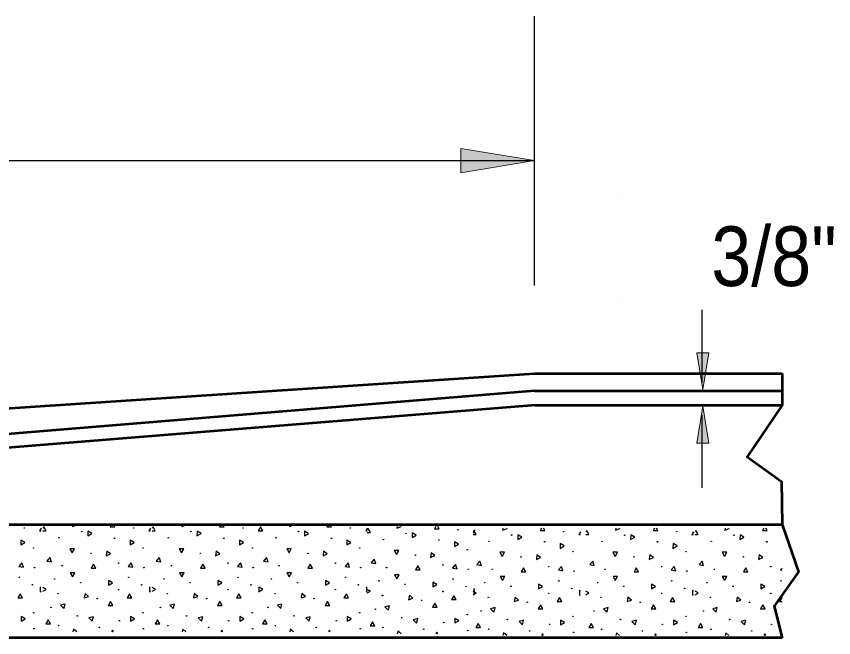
# Model space of a CAD drawing. Extents: x 75.6 to 110.9, y 28 to 50.
# Drawn here: x 100.368 to 102.421, y 39.251 to 40.813 of the extents above; entities that cross this region are included whole.
import ezdxf
from ezdxf.enums import TextEntityAlignment as Align

# ---------------------------------------------------------------- set-up
doc = ezdxf.new("R2010")
doc.units = 0
doc.header["$LTSCALE"] = 0.06
doc.layers.add('1', color=7, linetype='Continuous', lineweight=25)
doc.layers.add('3', color=7, linetype='Continuous', lineweight=13)

msp = doc.modelspace()

# ---------------------------------------------------------------- hatches: boundary and pattern name
at = {"layer": '3'}
for points in [[(101.48483, 40.48075), (101.48483, 40.41925), (101.66942, 40.45), (101.66942, 40.45)], [(102.07725, 39.96658), (102.108, 39.96658), (102.09258, 39.87433), (102.09258, 39.87433)], [(102.07725, 39.74), (102.108, 39.74), (102.09258, 39.83233), (102.09258, 39.83233)]]:
    msp.add_hatch(color=256, dxfattribs=at).paths.add_polyline_path(points)

# ---------------------------------------------------------------- linework, layer by layer
at = {"layer": '1'}
for p, q in [((101.66942, 40.13592), (101.66942, 40.81275)), ((98.68033, 40.45), (101.66942, 40.45)), ((100.4305, 39.52617), (100.42658, 39.51933)), ((100.42658, 39.51933), (100.4305, 39.51933)), ((100.437, 39.52933), (100.43508, 39.52617)), ((100.43508, 39.51933), (100.44283, 39.51933)), ((100.44283, 39.51933), (100.437, 39.52933)), ((100.51033, 39.535), (100.50958, 39.53033)), ((100.50958, 39.53033), (100.5205, 39.53433)), ((100.5205, 39.53433), (100.51983, 39.535)), ((100.60733, 39.535), (100.604, 39.52917)), ((100.604, 39.52917), (100.61558, 39.52917)), ((100.61558, 39.52917), (100.61225, 39.535)), ((100.70508, 39.52617), (100.70117, 39.51933)), ((100.70117, 39.51933), (100.70508, 39.51933)), ((100.71158, 39.52933), (100.70958, 39.52617)), ((100.70958, 39.51933), (100.71733, 39.51933)), ((100.71733, 39.51933), (100.71158, 39.52933)), ((100.78492, 39.535), (100.78408, 39.53033)), ((100.78408, 39.53033), (100.795, 39.53433)), ((100.795, 39.53433), (100.79433, 39.535)), ((100.88192, 39.535), (100.87858, 39.52917)), ((100.87858, 39.52917), (100.89025, 39.52917)), ((100.89025, 39.52917), (100.88683, 39.535)), ((100.97958, 39.52617), (100.97567, 39.51933)), ((100.97567, 39.51933), (100.97958, 39.51933)), ((100.98158, 39.52933), (100.97975, 39.52617)), ((100.97975, 39.51933), (100.98742, 39.51933)), ((100.98742, 39.51933), (100.98158, 39.52933)), ((101.055, 39.535), (101.05425, 39.53033)), ((101.05425, 39.53033), (101.06517, 39.53433)), ((101.06517, 39.53433), (101.06442, 39.535)), ((101.152, 39.535), (101.14858, 39.52917)), ((101.14858, 39.52917), (101.16025, 39.52917)), ((101.16025, 39.52917), (101.15692, 39.535)), ((101.24975, 39.52617), (101.24583, 39.51933)), ((101.24583, 39.51933), (101.24975, 39.51933)), ((101.25167, 39.52492), (101.24983, 39.52167)), ((101.2575, 39.51483), (101.25167, 39.52492)), ((101.325, 39.53042), (101.32425, 39.52592)), ((101.32425, 39.52592), (101.33525, 39.52992)), ((101.33525, 39.52992), (101.3345, 39.53042)), ((101.422, 39.53042), (101.41867, 39.52467)), ((101.41867, 39.52467), (101.43033, 39.52467)), ((101.43033, 39.52467), (101.427, 39.53042)), ((101.51725, 39.52033), (101.51542, 39.51708)), ((101.51983, 39.52167), (101.51583, 39.51483)), ((101.52308, 39.51033), (101.51725, 39.52033)), ((101.59058, 39.52592), (101.58983, 39.52133)), ((101.58983, 39.52133), (101.60083, 39.52533)), ((101.60083, 39.52533), (101.60008, 39.52592)), ((101.68758, 39.52592), (101.68425, 39.52017)), ((101.68425, 39.52017), (101.69592, 39.52017)), ((101.69592, 39.52017), (101.69258, 39.52592)), ((101.80083, 39.52033), (101.79892, 39.51708)), ((101.80658, 39.51033), (101.80083, 39.52033)), ((101.87425, 39.52592), (101.87342, 39.52133)), ((101.87342, 39.52133), (101.88433, 39.52533)), ((101.88433, 39.52533), (101.88358, 39.52592)), ((101.97125, 39.52592), (101.96783, 39.52017)), ((101.96783, 39.52017), (101.9795, 39.52017)), ((101.9795, 39.52017), (101.97617, 39.52592)), ((102.07542, 39.52033), (102.07358, 39.51708)), ((102.08125, 39.51033), (102.07542, 39.52033)), ((102.14883, 39.52592), (102.148, 39.52133)), ((102.148, 39.52133), (102.15892, 39.52533)), ((102.15892, 39.52533), (102.15825, 39.52592)), ((102.24583, 39.52592), (102.24242, 39.52017)), ((102.24242, 39.52017), (102.25408, 39.52017)), ((102.25408, 39.52017), (102.25075, 39.52592)), ((101.24983, 39.51483), (101.2575, 39.51483)), ((101.51542, 39.51033), (101.52308, 39.51033)), ((101.51583, 39.51483), (101.51983, 39.51483)), ((101.78542, 39.51708), (101.78142, 39.51033)), ((101.78142, 39.51033), (101.78542, 39.51033)), ((101.79892, 39.51033), (101.80658, 39.51033)), ((102.06892, 39.51708), (102.065, 39.51033)), ((102.065, 39.51033), (102.06892, 39.51033)), ((102.07358, 39.51033), (102.08125, 39.51033)), ((102.29183, 39.42575), (102.28783, 39.421)), ((102.28783, 39.421), (102.29183, 39.42033)), ((100.42825, 39.378), (100.42817, 39.36633)), ((100.42825, 39.378), (100.42817, 39.36633)), ((100.4305, 39.37658), (100.42825, 39.378)), ((100.4305, 39.37658), (100.42825, 39.378)), ((100.70283, 39.378), (100.70275, 39.36633)), ((100.70283, 39.378), (100.70275, 39.36633)), ((100.70508, 39.37658), (100.70283, 39.378)), ((100.70508, 39.37658), (100.70283, 39.378)), ((100.97733, 39.378), (100.97725, 39.36633)), ((100.97733, 39.378), (100.97725, 39.36633)), ((100.97958, 39.37658), (100.97733, 39.378)), ((100.97958, 39.37658), (100.97733, 39.378)), ((101.24742, 39.378), (101.24742, 39.36633)), ((101.24742, 39.378), (101.24742, 39.36633)), ((101.24975, 39.37658), (101.24742, 39.378)), ((101.24975, 39.37658), (101.24742, 39.378)), ((100.42817, 39.36633), (100.4305, 39.36767)), ((100.42817, 39.36633), (100.4305, 39.36767)), ((100.70275, 39.36633), (100.70508, 39.36767)), ((100.70275, 39.36633), (100.70508, 39.36767)), ((100.97725, 39.36633), (100.97958, 39.36767)), ((100.97725, 39.36633), (100.97958, 39.36767)), ((101.24742, 39.36633), (101.24975, 39.36767)), ((101.24742, 39.36633), (101.24975, 39.36767)), ((101.5175, 39.37342), (101.51742, 39.36175)), ((101.5175, 39.37342), (101.51742, 39.36175)), ((101.51742, 39.36175), (101.51983, 39.36317)), ((101.51742, 39.36175), (101.51983, 39.36317)), ((101.51983, 39.37208), (101.5175, 39.37342)), ((101.51983, 39.37208), (101.5175, 39.37342)), ((101.78308, 39.36892), (101.783, 39.35725)), ((101.78308, 39.36892), (101.783, 39.35725)), ((101.783, 39.35725), (101.78542, 39.35858)), ((101.783, 39.35725), (101.78542, 39.35858)), ((101.78542, 39.36758), (101.78308, 39.36892)), ((101.78542, 39.36758), (101.78308, 39.36892)), ((102.06658, 39.36892), (102.06658, 39.35725)), ((102.06658, 39.36892), (102.06658, 39.35725)), ((102.06892, 39.36758), (102.06658, 39.36892)), ((102.06892, 39.36758), (102.06658, 39.36892)), ((102.06658, 39.35725), (102.06892, 39.35858)), ((102.06658, 39.35725), (102.06892, 39.35858)), ((102.29092, 39.35175), (102.28508, 39.34175)), ((102.28508, 39.34175), (102.29183, 39.34175)), ((102.29183, 39.35025), (102.29092, 39.35175))]:
    msp.add_line(p, q, dxfattribs=at)
at = {"layer": '1', "lineweight": 53}
for p, q in [((98.66925, 39.71683), (101.66942, 39.91467)), ((101.66942, 39.91467), (102.29183, 39.91467)), ((101.66942, 39.87133), (98.662, 39.62308)), ((101.66942, 39.87133), (102.29183, 39.87133)), ((101.67208, 39.83542), (98.663, 39.59125)), ((101.66942, 39.83533), (102.29183, 39.83533)), ((98.193, 39.53508), (102.29183, 39.53508)), ((102.29183, 39.25075), (98.198, 39.25075))]:
    msp.add_line(p, q, dxfattribs=at)
msp.add_lwpolyline([(102.29183, 39.91467), (102.29183, 39.83533), (102.20375, 39.70517), (102.28983, 39.64367), (102.29183, 39.53508), (102.33292, 39.416), (102.27142, 39.32983), (102.29183, 39.25075)], dxfattribs=at)
at = {"layer": '1'}
for points in [[(100.5475, 39.50675), (100.55758, 39.51258), (100.54758, 39.51842)], [(100.822, 39.50675), (100.83217, 39.51258), (100.82208, 39.51842)], [(101.09217, 39.50675), (101.10225, 39.51258), (101.09225, 39.51842)], [(101.36225, 39.50225), (101.37225, 39.50808), (101.36225, 39.514)], [(101.62783, 39.49767), (101.63792, 39.50358), (101.62783, 39.50933)], [(101.91133, 39.49767), (101.92142, 39.50358), (101.91142, 39.50933)], [(102.18592, 39.49767), (102.196, 39.50358), (102.186, 39.50933)], [(100.37925, 39.48442), (100.38933, 39.49033), (100.37933, 39.49617)], [(100.65383, 39.48442), (100.66392, 39.49033), (100.65392, 39.49617)], [(100.92842, 39.48442), (100.9385, 39.49033), (100.9285, 39.49617)], [(101.1985, 39.48442), (101.20858, 39.49033), (101.19858, 39.49617)], [(101.46858, 39.48), (101.47858, 39.48575), (101.46858, 39.49167)], [(101.73417, 39.47533), (101.74425, 39.48125), (101.73425, 39.48708)], [(102.01767, 39.47533), (102.02783, 39.48125), (102.01783, 39.48708)], [(100.50858, 39.46425), (100.51442, 39.47433), (100.50275, 39.47433)], [(100.59425, 39.45667), (100.60483, 39.46158), (100.59525, 39.46825)], [(100.78308, 39.46425), (100.78892, 39.47433), (100.77725, 39.47433)], [(100.86883, 39.45667), (100.87933, 39.46158), (100.86983, 39.46825)], [(101.05325, 39.46425), (101.059, 39.47433), (101.04742, 39.47433)], [(101.13892, 39.45667), (101.14942, 39.46158), (101.13992, 39.46825)], [(101.32325, 39.45975), (101.32908, 39.46983), (101.31742, 39.46983)], [(101.40892, 39.45217), (101.4195, 39.45708), (101.41, 39.46375)], [(101.58883, 39.45517), (101.59467, 39.46533), (101.583, 39.46533)], [(101.67458, 39.44767), (101.68508, 39.45258), (101.67558, 39.45917)], [(101.87242, 39.45517), (101.87825, 39.46533), (101.86658, 39.46533)], [(101.95808, 39.44767), (101.96858, 39.45258), (101.95917, 39.45917)], [(102.147, 39.45517), (102.15283, 39.46533), (102.14125, 39.46533)], [(102.23267, 39.44767), (102.24325, 39.45258), (102.23375, 39.45917)], [(100.37483, 39.43), (100.38625, 39.428), (100.38225, 39.439)], [(100.44483, 39.44342), (100.45625, 39.44142), (100.45225, 39.45233)], [(100.64942, 39.43), (100.66083, 39.428), (100.65692, 39.439)], [(100.71933, 39.44342), (100.73083, 39.44142), (100.72683, 39.45233)], [(100.92392, 39.43), (100.93542, 39.428), (100.93142, 39.439)], [(100.98942, 39.44342), (101.00092, 39.44142), (100.99692, 39.45233)], [(101.194, 39.43), (101.2055, 39.428), (101.20158, 39.439)], [(101.2595, 39.439), (101.27092, 39.437), (101.267, 39.44783)], [(101.52508, 39.43433), (101.53658, 39.43233), (101.53258, 39.44333)], [(101.80858, 39.43433), (101.82008, 39.43233), (101.81617, 39.44333)], [(102.08325, 39.43433), (102.09467, 39.43233), (102.09075, 39.44333)], [(100.55592, 39.42533), (100.56758, 39.42533), (100.56183, 39.43542)], [(100.8305, 39.42533), (100.84217, 39.42533), (100.83633, 39.43542)], [(101.10058, 39.42533), (101.11225, 39.42533), (101.10642, 39.43542)], [(101.37058, 39.42092), (101.38225, 39.42092), (101.3765, 39.431)], [(101.46408, 39.42558), (101.47558, 39.42358), (101.47158, 39.4345)], [(101.63625, 39.41633), (101.64792, 39.41633), (101.64208, 39.42633)], [(101.72967, 39.421), (101.74117, 39.419), (101.73725, 39.43)], [(101.91983, 39.41633), (101.93142, 39.41633), (101.92558, 39.42633)], [(102.01325, 39.421), (102.02467, 39.419), (102.02075, 39.43)], [(102.19442, 39.41633), (102.206, 39.41633), (102.20025, 39.42633)], [(100.509, 39.40333), (100.51483, 39.4135), (100.50325, 39.4135)], [(100.78358, 39.40333), (100.78942, 39.4135), (100.77775, 39.4135)], [(101.05358, 39.40333), (101.0595, 39.4135), (101.04783, 39.4135)], [(101.32367, 39.39892), (101.32958, 39.409), (101.31792, 39.409)], [(101.58925, 39.39433), (101.59517, 39.40442), (101.5835, 39.40442)], [(101.87283, 39.39433), (101.87867, 39.40442), (101.867, 39.40442)], [(102.14742, 39.39433), (102.15325, 39.40442), (102.14158, 39.40442)], [(100.59992, 39.38283), (100.61, 39.38867), (100.59992, 39.3945)], [(100.87442, 39.38283), (100.88458, 39.38867), (100.8745, 39.3945)], [(101.14458, 39.38283), (101.15458, 39.38867), (101.14458, 39.3945)], [(101.41458, 39.37833), (101.42467, 39.38417), (101.41458, 39.39)], [(101.68025, 39.37375), (101.69025, 39.37967), (101.68025, 39.38542)], [(101.96375, 39.37375), (101.97383, 39.37967), (101.96383, 39.38542)], [(102.23833, 39.37375), (102.24842, 39.37967), (102.23842, 39.38542)], [(100.372, 39.35075), (100.38367, 39.35075), (100.37792, 39.36083)], [(100.53875, 39.3505), (100.54967, 39.3545), (100.54083, 39.362)], [(100.64658, 39.35075), (100.65825, 39.35075), (100.6525, 39.36083)], [(100.81325, 39.3505), (100.82425, 39.3545), (100.81533, 39.362)], [(100.92125, 39.35075), (100.93283, 39.35075), (100.927, 39.36083)], [(101.08342, 39.3505), (101.09433, 39.3545), (101.08542, 39.362)], [(101.19125, 39.35075), (101.20292, 39.35075), (101.19717, 39.36083)], [(101.35342, 39.346), (101.36442, 39.35), (101.3555, 39.35742)], [(101.46133, 39.34633), (101.473, 39.34633), (101.46725, 39.35633)], [(100.48758, 39.32417), (100.49058, 39.33533), (100.47933, 39.33233)], [(100.59917, 39.33192), (100.61083, 39.33192), (100.605, 39.342)], [(100.76217, 39.32417), (100.76517, 39.33533), (100.75392, 39.33233)], [(100.87367, 39.33192), (100.88533, 39.33192), (100.87958, 39.342)], [(101.03225, 39.32417), (101.03525, 39.33533), (101.024, 39.33233)], [(101.14383, 39.33192), (101.15542, 39.33192), (101.14958, 39.342)], [(101.41383, 39.32733), (101.4255, 39.32733), (101.41967, 39.33742)], [(101.619, 39.34142), (101.63, 39.34542), (101.62108, 39.35292)], [(101.72692, 39.34175), (101.73858, 39.34175), (101.73283, 39.35175)], [(101.90258, 39.34142), (101.91358, 39.34542), (101.90458, 39.35292)], [(102.0105, 39.34175), (102.02217, 39.34175), (102.01633, 39.35175)], [(102.17725, 39.34142), (102.18817, 39.34542), (102.17925, 39.35292)], [(101.30225, 39.31967), (101.30525, 39.33092), (101.294, 39.32792)], [(101.56792, 39.31508), (101.57092, 39.32633), (101.55958, 39.32333)], [(101.67942, 39.32283), (101.69108, 39.32283), (101.68525, 39.33292)], [(101.85142, 39.31508), (101.85442, 39.32633), (101.84325, 39.32333)], [(101.963, 39.32283), (101.97458, 39.32283), (101.96883, 39.33292)], [(102.126, 39.31508), (102.129, 39.32633), (102.11783, 39.32333)], [(102.23758, 39.32283), (102.24925, 39.32283), (102.24342, 39.33292)], [(100.38033, 39.29217), (100.39042, 39.298), (100.38042, 39.30375)], [(100.44225, 39.28533), (100.45383, 39.28533), (100.448, 39.29533)], [(100.55892, 39.29208), (100.56192, 39.30333), (100.55067, 39.30033)], [(100.65492, 39.29217), (100.665, 39.298), (100.655, 39.30375)], [(100.71675, 39.28533), (100.72842, 39.28533), (100.72258, 39.29533)], [(100.8335, 39.29208), (100.8365, 39.30333), (100.82525, 39.30033)], [(100.9295, 39.29217), (100.93958, 39.298), (100.92958, 39.30375)], [(100.98683, 39.28533), (100.9985, 39.28533), (100.99267, 39.29533)], [(101.10358, 39.29208), (101.10658, 39.30333), (101.09533, 39.30033)], [(101.19958, 39.29217), (101.20967, 39.298), (101.19958, 39.30375)], [(101.37358, 39.28758), (101.37658, 39.29892), (101.36542, 39.29592)], [(101.46958, 39.28767), (101.47975, 39.29342), (101.46967, 39.29933)], [(101.63925, 39.283), (101.64225, 39.29433), (101.631, 39.29133)], [(101.73525, 39.28308), (101.74533, 39.28892), (101.73525, 39.29475)], [(101.92283, 39.283), (101.92583, 39.29433), (101.91458, 39.29133)], [(102.01883, 39.28308), (102.02892, 39.28892), (102.01883, 39.29475)], [(102.19742, 39.283), (102.20042, 39.29433), (102.18917, 39.29133)], [(101.25692, 39.28083), (101.26858, 39.28083), (101.26275, 39.29092)], [(101.5225, 39.27633), (101.53417, 39.27633), (101.52833, 39.28633)], [(101.806, 39.27633), (101.81767, 39.27633), (101.81192, 39.28633)], [(102.08058, 39.27633), (102.09225, 39.27633), (102.0865, 39.28633)]]:
    msp.add_lwpolyline(points, close=True, dxfattribs=at)
for points in [[(100.43508, 39.36767), (100.44283, 39.37217), (100.43508, 39.37658)], [(100.70958, 39.36767), (100.71742, 39.37217), (100.70958, 39.37658)], [(100.97975, 39.36767), (100.9875, 39.37217), (100.97975, 39.37658)], [(101.24983, 39.36317), (101.25758, 39.36767), (101.24983, 39.37208)], [(101.51542, 39.35858), (101.52317, 39.36308), (101.51542, 39.36758)], [(101.79892, 39.35858), (101.80667, 39.36308), (101.79892, 39.36758)], [(102.07358, 39.35858), (102.08125, 39.36308), (102.07358, 39.36758)], [(100.51983, 39.265), (100.51158, 39.27183), (100.51033, 39.265)], [(100.51983, 39.265), (100.51158, 39.27183), (100.51033, 39.265)], [(100.61225, 39.265), (100.60983, 39.26925), (100.60733, 39.265)], [(100.79433, 39.265), (100.78617, 39.27183), (100.78492, 39.265)], [(100.79433, 39.265), (100.78617, 39.27183), (100.78492, 39.265)], [(100.88683, 39.265), (100.88442, 39.26925), (100.88192, 39.265)], [(101.06442, 39.265), (101.05625, 39.27183), (101.055, 39.265)], [(101.06442, 39.265), (101.05625, 39.27183), (101.055, 39.265)], [(101.15692, 39.265), (101.1545, 39.26925), (101.152, 39.265)], [(101.3345, 39.26042), (101.32625, 39.26733), (101.325, 39.26042)], [(101.3345, 39.26042), (101.32625, 39.26733), (101.325, 39.26042)], [(101.427, 39.26042), (101.42458, 39.26475), (101.422, 39.26042)], [(101.60008, 39.25592), (101.59192, 39.26275), (101.59058, 39.25592)], [(101.60008, 39.25592), (101.59192, 39.26275), (101.59058, 39.25592)], [(101.69258, 39.25592), (101.69017, 39.26017), (101.68758, 39.25592)], [(101.88358, 39.25592), (101.87542, 39.26275), (101.87425, 39.25592)], [(101.88358, 39.25592), (101.87542, 39.26275), (101.87425, 39.25592)], [(101.97617, 39.25592), (101.97367, 39.26017), (101.97125, 39.25592)], [(102.15825, 39.25592), (102.15, 39.26275), (102.14883, 39.25592)], [(102.15825, 39.25592), (102.15, 39.26275), (102.14883, 39.25592)], [(102.25075, 39.25592), (102.24825, 39.26017), (102.24583, 39.25592)]]:
    msp.add_lwpolyline(points, dxfattribs=at)
for centre in [(100.38831, 39.52638), (100.66291, 39.52638), (100.93746, 39.52638), (101.20756, 39.52638), (101.47761, 39.52188), (100.47549, 39.50184), (100.53239, 39.51745), (100.61494, 39.50073), (100.75004, 39.50184), (100.80694, 39.51745), (100.88949, 39.50073), (101.02014, 39.50184), (101.07704, 39.51745), (101.15959, 39.50073), (101.34709, 39.51295), (101.61269, 39.5084), (101.74321, 39.51733), (101.89624, 39.5084), (102.02676, 39.51733), (102.17084, 39.5084), (101.29019, 39.49734), (101.42964, 39.49623), (101.55579, 39.49279), (101.69524, 39.49168), (101.83934, 39.49279), (101.97879, 39.49168), (102.11394, 39.49279), (102.25339, 39.49168), (100.41176, 39.47619), (100.55581, 39.4628), (100.68636, 39.47619), (100.83036, 39.4628), (100.96091, 39.47619), (101.10046, 39.4628), (101.23101, 39.47619), (101.37051, 39.4583), (101.50106, 39.47169), (101.76666, 39.46714), (102.05021, 39.46714), (100.625, 39.43825), (100.89955, 39.43825), (101.16965, 39.43825), (101.63611, 39.45375), (101.91966, 39.45375), (102.19426, 39.45375), (100.41398, 39.42709), (100.48332, 39.43155), (100.68859, 39.42709), (100.75787, 39.43155), (100.96313, 39.42709), (101.02797, 39.43155), (101.23323, 39.42709), (101.29802, 39.42705), (101.4397, 39.43375), (101.50328, 39.42259), (101.56362, 39.4225), (101.7053, 39.4292), (101.76888, 39.41804), (101.84717, 39.4225), (101.98885, 39.4292), (102.05243, 39.41804), (102.12177, 39.4225), (102.26345, 39.4292), (100.37605, 39.40254), (100.46435, 39.39809), (100.65065, 39.40254), (100.7389, 39.39809), (100.9252, 39.40254), (101.009, 39.39809), (101.1953, 39.40254), (101.46535, 39.39804), (100.4084, 39.38358), (100.53016, 39.38916), (100.683, 39.38358), (100.80471, 39.38916), (100.95755, 39.38358), (101.07481, 39.38916), (101.22765, 39.38358), (101.27905, 39.39359), (101.34486, 39.38466), (101.4977, 39.37908), (101.54465, 39.38904), (101.61046, 39.38011), (101.73095, 39.39349), (101.8282, 39.38904), (101.89401, 39.38011), (102.0145, 39.39349), (102.1028, 39.38904), (102.16861, 39.38011), (102.2891, 39.39349), (100.47326, 39.36128), (100.625, 39.37131), (100.74781, 39.36128), (100.89955, 39.37131), (101.01791, 39.36128), (101.16965, 39.37131), (101.28796, 39.35678), (101.4397, 39.36681), (101.7053, 39.36226), (101.7633, 39.37453), (101.98885, 39.36226), (102.04685, 39.37453), (102.26345, 39.36226), (100.57145, 39.34899), (100.846, 39.34899), (101.1161, 39.34899), (101.38615, 39.34449), (101.55356, 39.35223), (101.65175, 39.33994), (101.83711, 39.35223), (101.9353, 39.33994), (102.11171, 39.35223), (102.2099, 39.33994), (100.41176, 39.31331), (100.45542, 39.3267), (100.68636, 39.31331), (100.72997, 39.3267), (100.96091, 39.31331), (101.00007, 39.3267), (101.23101, 39.31331), (101.27012, 39.3222), (101.53572, 39.31765), (101.81927, 39.31765), (102.09387, 39.31765), (100.52123, 39.30548), (100.62723, 39.29322), (100.79578, 39.30548), (100.90178, 39.29322), (101.06588, 39.30548), (101.17188, 39.29322), (101.33593, 39.30098), (101.50106, 39.30881), (101.60153, 39.29643), (101.76666, 39.30426), (101.88508, 39.29643), (102.05021, 39.30426), (102.15968, 39.29643), (100.41286, 39.27315), (100.47438, 39.28095), (100.57703, 39.27648), (100.68746, 39.27315), (100.74893, 39.28095), (100.85158, 39.27648), (100.96201, 39.27315), (101.01903, 39.28095), (101.12168, 39.27648), (101.23211, 39.27315), (101.28909, 39.27645), (101.44193, 39.28872), (101.70753, 39.28417), (101.99108, 39.28417), (102.26568, 39.28417), (101.39173, 39.27198), (101.50216, 39.26865), (101.55468, 39.2719), (101.65733, 39.26743), (101.76776, 39.2641), (101.83823, 39.2719), (101.94088, 39.26743), (102.05131, 39.2641), (102.11284, 39.2719), (102.21548, 39.26743)]:
    msp.add_circle(centre, 0.000647, dxfattribs=at)
at = {"layer": '3'}
for p, q in [((101.88883, 40.35942), (101.88892, 40.35942)), ((101.88883, 40.09842), (101.88892, 40.09842))]:
    msp.add_line(p, q, dxfattribs=at)
at = {"layer": '3', "lineweight": 25}
for p, q in [((102.09092, 39.89217), (102.09092, 40.075)), ((102.09092, 39.62758), (102.09092, 39.81033))]:
    msp.add_line(p, q, dxfattribs=at)
at = {"layer": '3'}
for points in [[(101.48483, 40.48075), (101.48483, 40.41925), (101.66942, 40.45), (101.66942, 40.45)], [(102.07725, 39.96658), (102.108, 39.96658), (102.09258, 39.87433), (102.09258, 39.87433)], [(102.07725, 39.74), (102.108, 39.74), (102.09258, 39.83233), (102.09258, 39.83233)]]:
    msp.add_lwpolyline(points, close=True, dxfattribs=at)

# ---------------------------------------------------------------- texts
at = {"layer": '1', "width": 0.9}
msp.add_text('3/8"', height=0.15, dxfattribs=at).set_placement((102.27137, 40.13475), align=Align.CENTER)

doc.saveas('drawing.dxf')
